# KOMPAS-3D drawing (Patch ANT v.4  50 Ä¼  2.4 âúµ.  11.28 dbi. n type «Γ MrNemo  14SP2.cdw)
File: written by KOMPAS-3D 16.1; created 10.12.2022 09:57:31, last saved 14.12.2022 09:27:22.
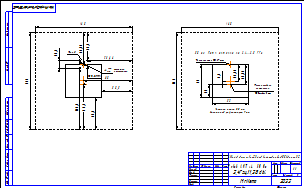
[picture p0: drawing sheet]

Sheet 1: custom format 500 x 310 mm, landscape

Title block, sheet 1: name: Patch ANT v.4  50 Ом / 2,4Ггц.11,28 dbi.; designation: https://www.lan23.ru/forum/node/851/page32; material: MrNemo; scale: 1:1; sheets: 1; organisation: 2022; stored path: G:\Patch ANT v.4  50 Ом от uve.cdw

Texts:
  высота над рефлектором 7мм
  50 ом Патч антенна на 2.4...2.5 ГГц
  Точка нулевого
  потенциала
  Ø Стойки 5mm
  Толщина патча 0,5 мм
  Точка запитки Ø 1,27 mm
  Type N
  Отверстие
  в рефлекторе
  Ø 2,5 mm
Dimensions and other numbers on the sheet: 52,5; 50,5; 80; 53,25; 12,7; 73,66; 46,9; 100,4; 160; 22; 59; 26,75; 55; 5,5; 32,25; 4; 74,5; 1:1; 1; 2,4Ггц.11,28 dbi.; 2022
